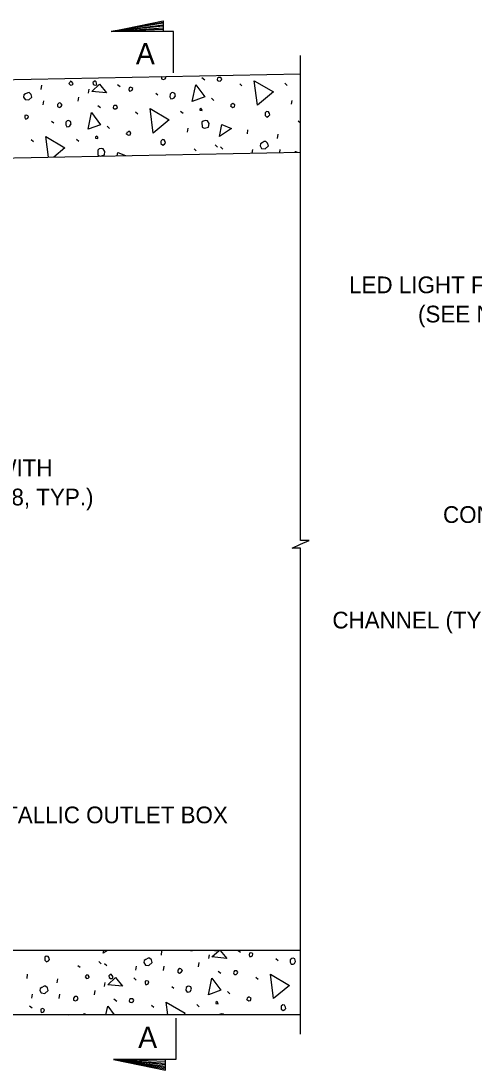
# Model space of a CAD drawing. Extents: x -1660015.2 to -1659984.9, y 2580594.2 to 2580616.7.
# Drawn here: x -1660007.03 to -1660002.94, y 2580605.21 to 2580614.7 of the extents above; entities that cross this region are included whole.
import ezdxf

# ---------------------------------------------------------------- set-up
doc = ezdxf.new("R2010")
doc.units = 0
for name, color, linetype in [('Miscellaneous', 7, 'Continuous'), ('Miscellaneous3', 7, 'Continuous'), ('PlotBorder_dp', 7, 'Continuous'), ('SheetLines_dp', 7, 'Continuous')]:
    doc.layers.add(name, color=color, linetype=linetype)

msp = doc.modelspace()

# ---------------------------------------------------------------- linework, layer by layer
at = {"layer": 'Miscellaneous'}
for p, q in [((-1660006.8506, 2580614.0777), (-1660006.8452, 2580614.1154)), ((-1660006.1589, 2580614.1233), (-1660006.1355, 2580614.1037)), ((-1660005.8895, 2580614.1903), (-1660005.8893, 2580614.1919)), ((-1660005.3964, 2580614.1852), (-1660005.3706, 2580614.1663)), ((-1660005.0553, 2580614.1291), (-1660005.035, 2580614.1113)), ((-1660004.6478, 2580614.1348), (-1660004.6245, 2580614.1151)), ((-1660006.5141, 2580613.9712), (-1660006.5087, 2580614.0088)), ((-1660006.4226, 2580614.0449), (-1660006.4165, 2580614.0801)), ((-1660005.8143, 2580614.0448), (-1660005.7946, 2580614.0293)), ((-1660006.8313, 2580613.9379), (-1660006.8259, 2580613.9756)), ((-1660006.3382, 2580613.9329), (-1660006.3124, 2580613.9139)), ((-1660005.3102, 2580613.9987), (-1660005.2892, 2580613.9784)), ((-1660004.5864, 2580613.9442), (-1660004.5803, 2580613.9794)), ((-1660005.997, 2580613.8768), (-1660005.9767, 2580613.8589)), ((-1660005.5896, 2580613.8824), (-1660005.5662, 2580613.8628)), ((-1660006.7561, 2580613.7924), (-1660006.7364, 2580613.777)), ((-1660006.252, 2580613.7463), (-1660006.231, 2580613.7261)), ((-1660005.5282, 2580613.6918), (-1660005.5221, 2580613.7271)), ((-1660004.5257, 2580613.7948), (-1660004.5054, 2580613.7769)), ((-1660006.5314, 2580613.6301), (-1660006.508, 2580613.6104)), ((-1660004.9858, 2580613.6767), (-1660004.9804, 2580613.7144)), ((-1660004.7134, 2580613.6358), (-1660004.708, 2580613.6735)), ((-1660006.9388, 2580613.6244), (-1660006.9185, 2580613.6066)), ((-1660005.4675, 2580613.5424), (-1660005.4472, 2580613.5246)), ((-1660005.2776, 2580613.5778), (-1660005.2567, 2580613.5575)), ((-1660005.2288, 2580613.5598), (-1660005.2079, 2580613.5395)), ((-1660004.9428, 2580613.5024), (-1660004.9373, 2580613.5344)), ((-1660004.6925, 2580613.5074), (-1660004.6887, 2580613.5337)), ((-1660006.4644, 2580613.472), (-1660006.4639, 2580613.4747)), ((-1660006.0356, 2580606.2934), (-1660006.0354, 2580606.2947)), ((-1660005.7633, 2580606.2525), (-1660005.7578, 2580606.2902)), ((-1660005.3352, 2580606.2197), (-1660005.3291, 2580606.2549)), ((-1660005.0675, 2580606.2947), (-1660005.0481, 2580606.2785)), ((-1660006.5173, 2580606.1591), (-1660006.497, 2580606.1413)), ((-1660006.3275, 2580606.1945), (-1660006.3065, 2580606.1742)), ((-1660006.2787, 2580606.1765), (-1660006.2577, 2580606.1562)), ((-1660005.9932, 2580606.1158), (-1660005.9872, 2580606.1511)), ((-1660005.7439, 2580606.1127), (-1660005.7385, 2580606.1504)), ((-1660005.4267, 2580606.1459), (-1660005.4213, 2580606.1836)), ((-1660004.7269, 2580606.2196), (-1660004.7073, 2580606.2041)), ((-1660006.9774, 2580606.041), (-1660006.972, 2580606.0787)), ((-1660006.0133, 2580606.0457), (-1660005.9899, 2580606.0261)), ((-1660005.2508, 2580606.1077), (-1660005.225, 2580606.0887)), ((-1660004.9097, 2580606.0516), (-1660004.8894, 2580606.0337)), ((-1660006.705, 2580606.0001), (-1660006.6996, 2580606.0378)), ((-1660006.277, 2580605.9673), (-1660006.2709, 2580606.0026)), ((-1660005.6687, 2580605.9672), (-1660005.6491, 2580605.9518)), ((-1660006.935, 2580605.8635), (-1660006.9289, 2580605.8987)), ((-1660006.6857, 2580605.8604), (-1660006.6803, 2580605.8981)), ((-1660006.3685, 2580605.8936), (-1660006.3631, 2580605.9313)), ((-1660006.1926, 2580605.8553), (-1660006.1668, 2580605.8364)), ((-1660005.1646, 2580605.9211), (-1660005.1437, 2580605.9009)), ((-1660006.9551, 2580605.7934), (-1660006.9317, 2580605.7738)), ((-1660005.8515, 2580605.7992), (-1660005.8311, 2580605.7814)), ((-1660005.444, 2580605.8048), (-1660005.4207, 2580605.7852)), ((-1660006.6105, 2580605.7149), (-1660006.6061, 2580605.7114))]:
    msp.add_line(p, q, dxfattribs=at)
for points in [[(-1660006.5987, 2580614.1323), (-1660006.5845, 2580614.1179), (-1660006.5693, 2580614.1194), (-1660006.5616, 2580614.1292), (-1660006.5629, 2580614.1341), (-1660006.5716, 2580614.1473), (-1660006.5832, 2580614.1519), (-1660006.591, 2580614.1421), (-1660006.5987, 2580614.1323)], [(-1660006.3931, 2580614.0605), (-1660006.3226, 2580614.126), (-1660006.2601, 2580614.047), (-1660006.3931, 2580614.0605)], [(-1660006.3797, 2580614.1262), (-1660006.3698, 2580614.1185), (-1660006.3565, 2580614.1169), (-1660006.3481, 2580614.1243), (-1660006.3483, 2580614.1346), (-1660006.3539, 2580614.1461), (-1660006.362, 2580614.1569), (-1660006.3752, 2580614.1481), (-1660006.3835, 2580614.1407), (-1660006.3797, 2580614.1262)], [(-1660005.761, 2580614.1936), (-1660005.7613, 2580614.1754), (-1660005.7436, 2580614.1673), (-1660005.7298, 2580614.1736), (-1660005.7185, 2580614.1895), (-1660005.7228, 2580614.1952)], [(-1660005.7603, 2580614.1945), (-1660005.761, 2580614.1936)], [(-1660005.4838, 2580613.9703), (-1660005.4517, 2580614.1212), (-1660005.3704, 2580614.011), (-1660005.4838, 2580613.9703)], [(-1660005.2547, 2580614.1585), (-1660005.2485, 2580614.155), (-1660005.2328, 2580614.154), (-1660005.2202, 2580614.1651), (-1660005.2173, 2580614.1737), (-1660005.226, 2580614.1869), (-1660005.2467, 2580614.1865), (-1660005.255, 2580614.1791), (-1660005.2573, 2580614.1682), (-1660005.2547, 2580614.1585)], [(-1660004.895, 2580613.9365), (-1660004.9229, 2580614.1568), (-1660004.7508, 2580614.0554), (-1660004.895, 2580613.9365)], [(-1660007.0084, 2580614.0095), (-1660006.9947, 2580613.9873), (-1660006.9624, 2580613.983), (-1660006.9332, 2580614.009), (-1660006.9396, 2580614.0331), (-1660006.9569, 2580614.0492), (-1660006.9696, 2580614.0484), (-1660006.99, 2580614.0377), (-1660007.0057, 2580614.0284), (-1660007.0084, 2580614.0095)], [(-1660006.0562, 2580614.0783), (-1660006.0523, 2580614.0638), (-1660006.0396, 2580614.0646), (-1660006.0282, 2580614.0703), (-1660006.0224, 2580614.0874), (-1660006.0292, 2580614.0933), (-1660006.0408, 2580614.098), (-1660006.0553, 2580614.0941), (-1660006.0562, 2580614.0783)], [(-1660005.685, 2580614.0354), (-1660005.6864, 2580614.0118), (-1660005.6764, 2580613.9937), (-1660005.6588, 2580613.9959), (-1660005.6474, 2580614.0015), (-1660005.6368, 2580614.0199), (-1660005.6426, 2580614.0416), (-1660005.6604, 2580614.0498), (-1660005.6724, 2580614.0466), (-1660005.685, 2580614.0354)], [(-1660006.7028, 2580613.9413), (-1660006.7031, 2580613.9231), (-1660006.6854, 2580613.9149), (-1660006.6715, 2580613.9212), (-1660006.6603, 2580613.9372), (-1660006.6683, 2580613.9479), (-1660006.6751, 2580613.9539), (-1660006.6861, 2580613.9561), (-1660006.6909, 2580613.9548), (-1660006.7028, 2580613.9413)], [(-1660006.1964, 2580613.9062), (-1660006.1903, 2580613.9026), (-1660006.1745, 2580613.9017), (-1660006.162, 2580613.9128), (-1660006.1591, 2580613.9213), (-1660006.1678, 2580613.9345), (-1660006.1884, 2580613.9342), (-1660006.1968, 2580613.9268), (-1660006.199, 2580613.9158), (-1660006.1964, 2580613.9062)], [(-1660005.1355, 2580613.9264), (-1660005.1172, 2580613.9158), (-1660005.1027, 2580613.9197), (-1660005.0976, 2580613.9392), (-1660005.1166, 2580613.9522), (-1660005.1249, 2580613.9448), (-1660005.134, 2580613.9398), (-1660005.1355, 2580613.9264), (-1660005.1368, 2580613.9313)], [(-1660006.998, 2580613.826), (-1660006.9941, 2580613.8115), (-1660006.9814, 2580613.8123), (-1660006.97, 2580613.8179), (-1660006.9642, 2580613.835), (-1660006.971, 2580613.841), (-1660006.9826, 2580613.8456), (-1660006.9971, 2580613.8417), (-1660006.998, 2580613.826)], [(-1660006.4255, 2580613.7179), (-1660006.3935, 2580613.8689), (-1660006.3122, 2580613.7587), (-1660006.4255, 2580613.7179)], [(-1660005.8367, 2580613.6842), (-1660005.8647, 2580613.9045), (-1660005.6926, 2580613.803), (-1660005.8367, 2580613.6842)], [(-1660005.4157, 2580613.8902), (-1660005.3945, 2580613.8881), (-1660005.397, 2580613.8978), (-1660005.4051, 2580613.9086), (-1660005.4159, 2580613.9005), (-1660005.4157, 2580613.8902)], [(-1660004.8251, 2580613.8595), (-1660004.8254, 2580613.8413), (-1660004.8088, 2580613.8276), (-1660004.7932, 2580613.837), (-1660004.7831, 2580613.8475), (-1660004.7863, 2580613.8595), (-1660004.7957, 2580613.8751), (-1660004.8121, 2580613.8785), (-1660004.8247, 2580613.8674), (-1660004.8251, 2580613.8595)], [(-1660006.6268, 2580613.7831), (-1660006.6282, 2580613.7594), (-1660006.6182, 2580613.7414), (-1660006.6006, 2580613.7435), (-1660006.5892, 2580613.7492), (-1660006.5786, 2580613.7675), (-1660006.5844, 2580613.7893), (-1660006.6021, 2580613.7974), (-1660006.6142, 2580613.7942), (-1660006.6268, 2580613.7831)], [(-1660005.3969, 2580613.7813), (-1660005.3956, 2580613.7377), (-1660005.3748, 2580613.7277), (-1660005.3627, 2580613.731), (-1660005.3361, 2580613.7381), (-1660005.3318, 2580613.7703), (-1660005.3462, 2580613.7949), (-1660005.365, 2580613.7976), (-1660005.3844, 2580613.7925), (-1660005.3969, 2580613.7813)], [(-1660005.2383, 2580613.653), (-1660005.2152, 2580613.7601), (-1660005.1279, 2580613.724), (-1660005.2383, 2580613.653)], [(-1660006.7828, 2580613.4656), (-1660006.8065, 2580613.6521), (-1660006.6344, 2580613.5507), (-1660006.7365, 2580613.4665)], [(-1660006.3575, 2580613.6378), (-1660006.3362, 2580613.6358), (-1660006.3388, 2580613.6454), (-1660006.3469, 2580613.6562), (-1660006.3577, 2580613.6481), (-1660006.3575, 2580613.6378)], [(-1660006.0773, 2580613.6741), (-1660006.059, 2580613.6635), (-1660006.0445, 2580613.6674), (-1660006.0393, 2580613.6868), (-1660006.0584, 2580613.6999), (-1660006.0667, 2580613.6924), (-1660006.0757, 2580613.6874), (-1660006.0773, 2580613.6741), (-1660006.0786, 2580613.6789)], [(-1660006.3387, 2580613.529), (-1660006.3373, 2580613.4854), (-1660006.3166, 2580613.4754), (-1660006.3045, 2580613.4786), (-1660006.2779, 2580613.4857), (-1660006.2736, 2580613.518), (-1660006.288, 2580613.5426), (-1660006.3068, 2580613.5453), (-1660006.3261, 2580613.5401), (-1660006.3387, 2580613.529)], [(-1660005.7669, 2580613.6071), (-1660005.7672, 2580613.5889), (-1660005.7506, 2580613.5753), (-1660005.735, 2580613.5846), (-1660005.7249, 2580613.5951), (-1660005.7281, 2580613.6072), (-1660005.7375, 2580613.6228), (-1660005.7539, 2580613.6262), (-1660005.7664, 2580613.615), (-1660005.7669, 2580613.6071)], [(-1660004.8712, 2580613.5676), (-1660004.8575, 2580613.5454), (-1660004.8252, 2580613.5411), (-1660004.796, 2580613.5671), (-1660004.8024, 2580613.5912), (-1660004.8197, 2580613.6073), (-1660004.8324, 2580613.6065), (-1660004.8528, 2580613.5958), (-1660004.8685, 2580613.5865), (-1660004.8712, 2580613.5676)], [(-1660006.1634, 2580613.478), (-1660006.157, 2580613.5078), (-1660006.0886, 2580613.4795)], [(-1660004.5363, 2580613.5105), (-1660004.5379, 2580613.512), (-1660004.5489, 2580613.5142), (-1660004.5537, 2580613.5129), (-1660004.5562, 2580613.5101)], [(-1660006.8168, 2580606.2238), (-1660006.8171, 2580606.2056), (-1660006.8005, 2580606.192), (-1660006.7848, 2580606.2013), (-1660006.7747, 2580606.2118), (-1660006.7779, 2580606.2239), (-1660006.7873, 2580606.2395), (-1660006.8037, 2580606.2429), (-1660006.8163, 2580606.2317), (-1660006.8168, 2580606.2238)], [(-1660006.2881, 2580606.2697), (-1660006.2827, 2580606.2947)], [(-1660006.2493, 2580606.2947), (-1660006.2881, 2580606.2697)], [(-1660005.4991, 2580606.2947), (-1660005.4971, 2580606.2927), (-1660005.482, 2580606.2942), (-1660005.4816, 2580606.2947)], [(-1660005.3057, 2580606.2353), (-1660005.2418, 2580606.2947)], [(-1660005.2305, 2580606.2947), (-1660005.1727, 2580606.2218), (-1660005.3057, 2580606.2353)], [(-1660005.2842, 2580606.2947), (-1660005.2825, 2580606.2933), (-1660005.2691, 2580606.2917), (-1660005.2657, 2580606.2947)], [(-1660004.9689, 2580606.2531), (-1660004.965, 2580606.2386), (-1660004.9523, 2580606.2394), (-1660004.9408, 2580606.2451), (-1660004.9351, 2580606.2622), (-1660004.9418, 2580606.2681), (-1660004.9534, 2580606.2728), (-1660004.9679, 2580606.2689), (-1660004.9689, 2580606.2531)], [(-1660005.921, 2580606.1843), (-1660005.9073, 2580606.1621), (-1660005.8751, 2580606.1578), (-1660005.8458, 2580606.1838), (-1660005.8523, 2580606.2079), (-1660005.8695, 2580606.224), (-1660005.8822, 2580606.2232), (-1660005.9027, 2580606.2125), (-1660005.9183, 2580606.2032), (-1660005.921, 2580606.1843)], [(-1660004.5976, 2580606.2102), (-1660004.599, 2580606.1866), (-1660004.589, 2580606.1685), (-1660004.5715, 2580606.1706), (-1660004.5601, 2580606.1763), (-1660004.5494, 2580606.1947), (-1660004.5553, 2580606.2164), (-1660004.573, 2580606.2246), (-1660004.5851, 2580606.2214), (-1660004.5976, 2580606.2102)], [(-1660006.4531, 2580606.0547), (-1660006.4389, 2580606.0404), (-1660006.4238, 2580606.0419), (-1660006.416, 2580606.0517), (-1660006.4173, 2580606.0565), (-1660006.426, 2580606.0697), (-1660006.4376, 2580606.0744), (-1660006.4454, 2580606.0645), (-1660006.4531, 2580606.0547)], [(-1660006.2475, 2580605.983), (-1660006.1771, 2580606.0484), (-1660006.1145, 2580605.9694), (-1660006.2475, 2580605.983)], [(-1660006.2341, 2580606.0487), (-1660006.2242, 2580606.041), (-1660006.2109, 2580606.0394), (-1660006.2025, 2580606.0468), (-1660006.2027, 2580606.0571), (-1660006.2083, 2580606.0685), (-1660006.2164, 2580606.0793), (-1660006.2296, 2580606.0706), (-1660006.2379, 2580606.0632), (-1660006.2341, 2580606.0487)], [(-1660005.6154, 2580606.1161), (-1660005.6157, 2580606.0979), (-1660005.598, 2580606.0897), (-1660005.5842, 2580606.096), (-1660005.5729, 2580606.112), (-1660005.581, 2580606.1227), (-1660005.5877, 2580606.1287), (-1660005.5987, 2580606.1309), (-1660005.6035, 2580606.1296), (-1660005.6154, 2580606.1161)], [(-1660005.3382, 2580605.8927), (-1660005.3062, 2580606.0437), (-1660005.2249, 2580605.9335), (-1660005.3382, 2580605.8927)], [(-1660005.1091, 2580606.0809), (-1660005.103, 2580606.0774), (-1660005.0872, 2580606.0765), (-1660005.0746, 2580606.0876), (-1660005.0717, 2580606.0961), (-1660005.0805, 2580606.1093), (-1660005.1011, 2580606.109), (-1660005.1094, 2580606.1016), (-1660005.1117, 2580606.0906), (-1660005.1091, 2580606.0809)], [(-1660004.7494, 2580605.859), (-1660004.7773, 2580606.0793), (-1660004.6052, 2580605.9778), (-1660004.7494, 2580605.859)], [(-1660006.8628, 2580605.932), (-1660006.8491, 2580605.9098), (-1660006.8169, 2580605.9055), (-1660006.7876, 2580605.9314), (-1660006.794, 2580605.9556), (-1660006.8113, 2580605.9717), (-1660006.824, 2580605.9708), (-1660006.8445, 2580605.9602), (-1660006.8601, 2580605.9508), (-1660006.8628, 2580605.932)], [(-1660005.9106, 2580606.0008), (-1660005.9068, 2580605.9863), (-1660005.894, 2580605.9871), (-1660005.8826, 2580605.9927), (-1660005.8768, 2580606.0098), (-1660005.8836, 2580606.0158), (-1660005.8952, 2580606.0204), (-1660005.9097, 2580606.0165), (-1660005.9106, 2580606.0008)], [(-1660005.5394, 2580605.9579), (-1660005.5408, 2580605.9342), (-1660005.5308, 2580605.9162), (-1660005.5133, 2580605.9183), (-1660005.5018, 2580605.9239), (-1660005.4912, 2580605.9423), (-1660005.497, 2580605.9641), (-1660005.5148, 2580605.9722), (-1660005.5268, 2580605.969), (-1660005.5394, 2580605.9579)], [(-1660006.5572, 2580605.8637), (-1660006.5575, 2580605.8455), (-1660006.5398, 2580605.8374), (-1660006.5259, 2580605.8437), (-1660006.5147, 2580605.8596), (-1660006.5228, 2580605.8704), (-1660006.5295, 2580605.8763), (-1660006.5405, 2580605.8786), (-1660006.5453, 2580605.8773), (-1660006.5572, 2580605.8637)], [(-1660006.0509, 2580605.8286), (-1660006.0447, 2580605.8251), (-1660006.029, 2580605.8241), (-1660006.0164, 2580605.8352), (-1660006.0135, 2580605.8438), (-1660006.0222, 2580605.857), (-1660006.0428, 2580605.8566), (-1660006.0512, 2580605.8492), (-1660006.0534, 2580605.8383), (-1660006.0509, 2580605.8286)], [(-1660004.99, 2580605.8489), (-1660004.9716, 2580605.8383), (-1660004.9571, 2580605.8421), (-1660004.952, 2580605.8616), (-1660004.971, 2580605.8747), (-1660004.9794, 2580605.8672), (-1660004.9884, 2580605.8622), (-1660004.99, 2580605.8489), (-1660004.9913, 2580605.8537)], [(-1660006.8524, 2580605.7484), (-1660006.8485, 2580605.7339), (-1660006.8358, 2580605.7347), (-1660006.8244, 2580605.7404), (-1660006.8186, 2580605.7575), (-1660006.8254, 2580605.7634), (-1660006.837, 2580605.7681), (-1660006.8515, 2580605.7642), (-1660006.8524, 2580605.7484)], [(-1660006.2649, 2580605.7114), (-1660006.2479, 2580605.7913), (-1660006.189, 2580605.7114)], [(-1660005.7045, 2580605.7114), (-1660005.7191, 2580605.8269), (-1660005.547, 2580605.7255), (-1660005.5641, 2580605.7114)], [(-1660005.2701, 2580605.8126), (-1660005.2489, 2580605.8106), (-1660005.2515, 2580605.8202), (-1660005.2595, 2580605.831), (-1660005.2703, 2580605.8229), (-1660005.2701, 2580605.8126)], [(-1660004.6796, 2580605.7819), (-1660004.6799, 2580605.7637), (-1660004.6633, 2580605.7501), (-1660004.6476, 2580605.7594), (-1660004.6375, 2580605.7699), (-1660004.6407, 2580605.782), (-1660004.6501, 2580605.7976), (-1660004.6665, 2580605.8009), (-1660004.6791, 2580605.7898), (-1660004.6796, 2580605.7819)], [(-1660006.4388, 2580605.7114), (-1660006.4388, 2580605.7117), (-1660006.4566, 2580605.7199), (-1660006.4686, 2580605.7167), (-1660006.4745, 2580605.7114)], [(-1660005.1971, 2580605.7114), (-1660005.2006, 2580605.7174), (-1660005.2194, 2580605.7201), (-1660005.2388, 2580605.7149), (-1660005.2427, 2580605.7114)]]:
    msp.add_lwpolyline(points, dxfattribs=at)
at = {"layer": 'Miscellaneous3'}
for p, q in [((-1660014.6931, 2580614.0158), (-1660004.5045, 2580614.2196)), ((-1660007.4989, 2580613.4513), (-1660004.5045, 2580613.5112)), ((-1660004.5045, 2580606.2947), (-1660008.2489, 2580606.2947)), ((-1660004.5045, 2580605.7114), (-1660008.7906, 2580605.7114))]:
    msp.add_line(p, q, dxfattribs=at)
at = {"layer": 'SheetLines_dp'}
for p, q in [((-1660006.2165, 2580614.6034), (-1660005.7478, 2580614.6859)), ((-1660005.7478, 2580614.6759), (-1660006.2165, 2580614.6034)), ((-1660006.2165, 2580614.6034), (-1660005.7478, 2580614.6634)), ((-1660005.7478, 2580614.6496), (-1660006.2165, 2580614.6034)), ((-1660006.2165, 2580614.6034), (-1660005.7478, 2580614.6359)), ((-1660005.7478, 2580614.6209), (-1660006.2165, 2580614.6034)), ((-1660005.7271, 2580605.2889), (-1660006.1958, 2580605.3064)), ((-1660006.1958, 2580605.3064), (-1660005.7271, 2580605.2739)), ((-1660005.7271, 2580605.2602), (-1660006.1958, 2580605.3064)), ((-1660006.1958, 2580605.3064), (-1660005.7271, 2580605.2464)), ((-1660005.7271, 2580605.2339), (-1660006.1958, 2580605.3064)), ((-1660006.1958, 2580605.3064), (-1660005.7271, 2580605.2239))]:
    msp.add_line(p, q, dxfattribs=at)
for points in [[(-1660005.654, 2580614.2284), (-1660005.654, 2580614.6034), (-1660006.2165, 2580614.6034), (-1660005.7478, 2580614.6971), (-1660005.7478, 2580614.6034)], [(-1660004.5045, 2580605.5366), (-1660004.5045, 2580609.9317), (-1660004.582, 2580609.9317), (-1660004.5045, 2580609.9655), (-1660004.427, 2580609.9992), (-1660004.5045, 2580609.9992), (-1660004.5045, 2580614.3862)], [(-1660005.6333, 2580605.6814), (-1660005.6333, 2580605.3064), (-1660006.1958, 2580605.3064), (-1660005.7271, 2580605.2127), (-1660005.7271, 2580605.3064)]]:
    msp.add_lwpolyline(points, dxfattribs=at)

# ---------------------------------------------------------------- texts
at = {"layer": 'PlotBorder_dp'}
for s, height, p in [('A', 0.192, (-1660005.9935, 2580614.3057)), ('CONDUIT (120V)', 0.1512, (-1660003.2171, 2580610.159)), ('NONMETALLIC OUTLET BOX', 0.1512, (-1660007.9373, 2580607.4435)), ('A', 0.192, (-1660005.9728, 2580605.4121))]:
    msp.add_text(s, height=height, dxfattribs=at).set_placement(p)
at = {"layer": 'SheetLines_dp'}
for s, p in [('LED LIGHT FIXTURE ', (-1660004.0659, 2580612.2358)), ('(SEE NOTE 15)', (-1660003.4433, 2580611.9718)), ('SINGLE HOLE STRAPS WITH', (-1660009.5339, 2580610.5814)), ('FASTENERS (SEE NOTE 8, TYP.)', (-1660009.5339, 2580610.3174)), ('CHANNEL (TYP.)', (-1660004.217, 2580609.2049))]:
    msp.add_text(s, height=0.1512, dxfattribs=at).set_placement(p)

doc.saveas('drawing.dxf')
